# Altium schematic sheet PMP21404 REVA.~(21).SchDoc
size 431 x 279 mm; Date: Not shown in title block; ApprovedBy: Not shown in title block; CheckedBy: Not shown in title block; Author: Not shown in title block; CompanyName: Not shown in title block; Engineer: Not shown in title block; Organization: Not shown in title block; Address1: Not shown in title block; Address2: Not shown in title block; Address3: Not shown in title block; Address4: Not shown in title block; DocumentNumber: 1; Revision: Use project parameter SCH_Rev; SheetNumber: 1; SheetTotal: 1; PageSetup: Record=PageOptions¦CenterHorizontal=True¦CenterVertical=True¦PrintScale=1.00¦XCorrection=1.00¦YCorrection=1.00¦PrintKind=0¦BorderSize=5000000¦LeftOffset=0¦BottomOffset=0¦Orientation=2¦PaperLength=1000¦PaperWidth=1000¦Scale=100¦PaperSource=15¦PrintQuality=600¦MediaType=1¦DitherType=10¦PaperKind=Letter¦PrintScaleMode=1
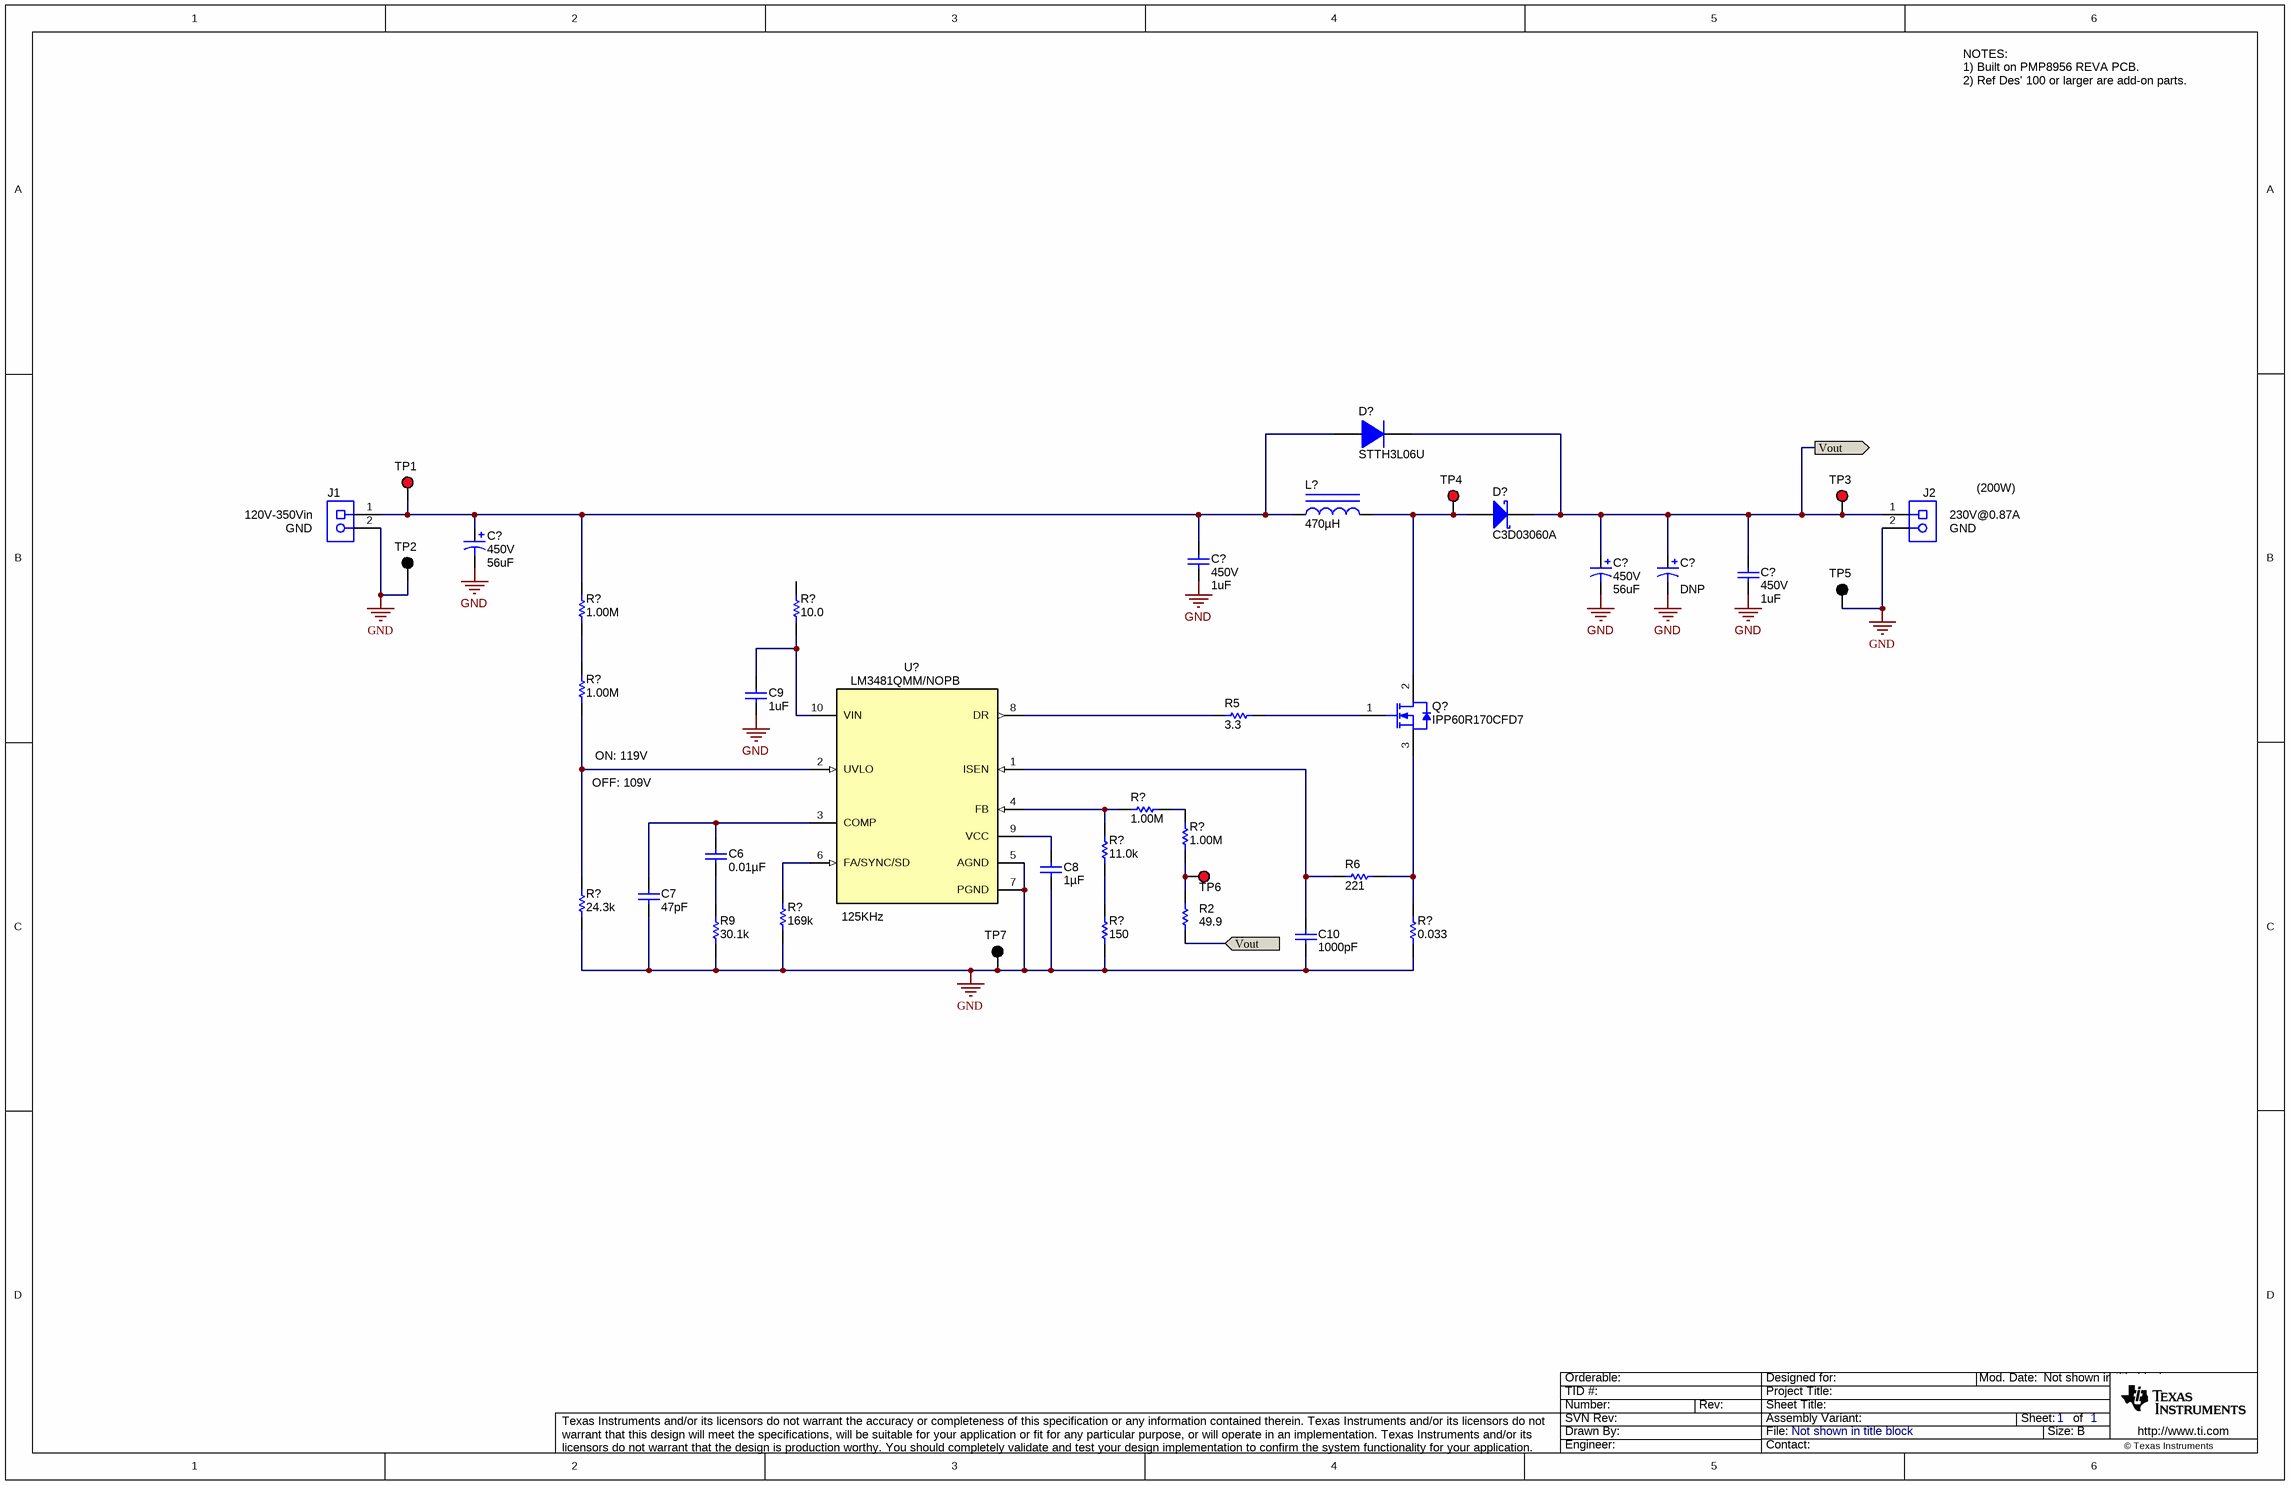
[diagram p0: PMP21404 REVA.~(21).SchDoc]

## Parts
(Parts that share a designator on the sheet are numbered #1, #2 ... from top to bottom, then left to right.)
C6  ValueDisplayed: 0.01µF  [0603]  (hidden comment: C1608X7R1H103K)
C7  ValueDisplayed: 47pF  [0603]  (hidden comment: C1608C0G1H470J)
C8  ValueDisplayed: 1µF  [0603L]  (hidden comment: C1608X7R1C105K)
C9  ValueDisplayed: 1uF  [0805L]  (hidden comment: Capacitor)
C10  ValueDisplayed: 1000pF  [0603L]  (hidden comment: C1608X7R1H102K)
C?#1  VDC_V: 450V  ValueDisplayed: 56uF  [Nichicon_2000x2500_Snap]  (hidden comment: LLS2W560MELY)
C?#2  VDC_V: 450V  ValueDisplayed: 1uF  [MPK_1800x950]  (hidden comment: 450MPK105J)
C?#3  VDC_V: 450V  ValueDisplayed: 56uF  [Nichicon_2000x2500_Snap]  (hidden comment: LLS2W560MELY)
C?#4  ValueDisplayed: DNP  [Nichicon_2000x2500_Snap]
C?#5  VDC_V: 450V  ValueDisplayed: 1uF  [MPK_1800x950]  (hidden comment: 450MPK105J)
D?#1  STTH3L06U  [SMB]
D?#2  C3D03060A  [TO-220-2]
J1  Receptacle_2x1  [TERM_BLK_ED555-2DS]  (value not drawn)
J2  Receptacle_2x1  [TERM_BLK_ED555-2DS]  (value not drawn)
L?  ValueDisplayed: 470µH  [Renco_RL1256-3_Pitch_750]  (hidden comment: RL-1256-3-470)
Q?  IPP60R170CFD7  [TO-220AB]
R2  value 49.9  [0603L]  (hidden comment: Resistor)
R5  ValueDisplayed: 3.3  [0603]  (hidden comment: Resistor)
R6  value 221  [0603L]  (hidden comment: Resistor)
R9  ValueDisplayed: 30.1k  [0603]  (hidden comment: Resistor)
R?#1  ValueDisplayed: 1.00M  [1206]  (hidden comment: CRCW12061M00FKEA)
R?#2  ValueDisplayed: 10.0  [0603]  (hidden comment: CRCW060310R0FKEA)
R?#3  ValueDisplayed: 1.00M  [1206]  (hidden comment: CRCW12061M00FKEA)
R?#4  ValueDisplayed: 1.00M  [1206]  (hidden comment: CRCW12061M00FKEA)
R?#5  ValueDisplayed: 1.00M  [1206]  (hidden comment: CRCW12061M00FKEA)
R?#6  ValueDisplayed: 11.0k  [0603]  (hidden comment: CRCW060311K0FKEA)
R?#7  ValueDisplayed: 24.3k  [0603]  (hidden comment: CRCW060324K3FKEA)
R?#8  ValueDisplayed: 169k  [0603]  (hidden comment: CRCW0603169KFKEA)
R?#9  ValueDisplayed: 150  [0603]  (hidden comment: CRCW0603150RFKEA)
R?#10  ValueDisplayed: 0.033  [1206]  (hidden comment: ERJ-8CWFR033V)
TP1  5000  [Keystone5000]  (value not drawn)
TP2  5001  [Keystone5001]  (value not drawn)
TP3  5000  [Keystone5000]  (value not drawn)
TP4  5000  [Keystone5000]  (value not drawn)
TP5  5001  [Keystone5001]  (value not drawn)
TP6  5000  [Keystone5000]  (value not drawn)
TP7  5001  [Keystone5001]  (value not drawn)
U?  LM3481QMM/NOPB  [DGS0010A_N]

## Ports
Vout

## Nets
GND: C7.2 C8.2 C9.2 C10.2 C?#1.2(-) C?#2.2 C?#3.2(-) C?#4.2(-) C?#5.2 J1.2 J2.2 R9.1 R?#7.1 R?#8.1 R?#9.1 R?#10.1 TP2.1 TP5.1 TP7.1 U?.5(AGND) U?.7(PGND)
Vout: C?#3.1(+) C?#4.1(+) C?#5.1 D?#1.1(K) D?#2.1(K) J2.1 R2.1 TP3.1 ; port Vout
NetC6_1: C6.1 C7.1 U?.3(COMP)
NetC6_2: C6.2 R9.2
NetC8_1: C8.1 U?.9(VCC)
NetC9_1: C9.1 R?#2.1 U?.10(VIN)
NetC10_1: C10.1 R6.2 U?.1(ISEN)
NetC?#1_1: C?#1.1(+) C?#2.1 D?#1.2(A) J1.1 L?.1 R?#1.2 TP1.1
NetD?#2_2: D?#2.2(A) L?.2 Q?.2(D) TP4.1
NetQ?_1: Q?.1(G) R5.2
NetQ?_3: Q?.3(S) R6.1 R?#10.2
NetR2_2: R2.2 R?#5.1 TP6.1
NetR5_1: R5.1 U?.8(DR)
NetR?#1_1: R?#1.1 R?#3.2
NetR?#3_1: R?#3.1 R?#7.2 U?.2(UVLO)
NetR?#4_1: R?#4.1 R?#6.2 U?.4(FB)
NetR?#4_2: R?#4.2 R?#5.2
NetR?#6_1: R?#6.1 R?#9.2
NetR?#8_2: R?#8.2 U?.6(FA/SYNC/SD)

Not connected (* = marked no-connect by the designer): R?#2 2

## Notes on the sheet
- NOTES:
  1) Built on PMP8956 REVA PCB.
  2) Ref Des' 100 or larger are add-on parts.
- (200W)
- (near J1) 120V-350Vin
- (near J1) GND
- (near J2) 230V@0.87A
- (near J2) GND
- (near R?#3) ON: 119V
- OFF: 109V
- (near U?) 125KHz

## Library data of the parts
C6 = C1608X7R1H103K: CAP, CERM, 0.01uF, 50V, +/-10%, X7R, 0603; Manufacturer: TDK; Polarized: N; CompType: Capacitor; U/M: EA; Cap_F: 0.00000001; Tolerance_%: 10; ESR_Ohm: 0.0539; Value1: 0.0539 ohm; VDC_V: 50; TaMin_C: -55; TaMax_C: 125
C7 = C1608C0G1H470J: CAP, CERM, 47pF, 50V, +/-5%, C0G/NP0, 0603; Manufacturer: TDK; Polarized: N; CompType: Capacitor; U/M: EA; Cap_F: 0.000000000047; Tolerance_%: 5; ESR_Ohm: 0.22; Value1: 0.22 ohm; VDC_V: 50; TaMin_C: -55; TaMax_C: 125
C8 = C1608X7R1C105K: CAP, CERM, 1uF, 16V, +/-10%, X7R, 0603; Manufacturer: TDK; Polarized: N; CompType: Capacitor; U/M: EA; Cap_F: 0.000001; Tolerance_%: 10; ESR_Ohm: 0.0057; Value1: 0.0057 ohm; VDC_V: 16; TaMin_C: -55; TaMax_C: 125; Cap_Case: 0603
C9 = CMP-0008350-2: CAP, CERM, 1 uF, 50 V, +/- 10%, X7R, 0805; PartNumber: GRM21BR71H105KA12L; Manufacturer: MuRata; Polarized: N; Value: 1uF; U/M: EA; Cap_F: 1µF; Value1: Unknown; VDC_V: 50V; TaMin_C: -55°C; TaMax_C: 125°C; Cap_Case: 0805; AEC Category: Q200; SizeArea_mm2: 2.5; SizeAreaWB_mm2: 6.75; SizeX_mm: 2; SizeY_mm: 1.25; SizeZ_mm: 1.45
C10 = C1608X7R1H102K: CAP, CERM, 1000pF, 50V, +/-10%, X7R, 0603; Manufacturer: TDK; Polarized: N; CompType: Capacitor; U/M: EA; Cap_F: 0.000000001; Tolerance_%: 10; ESR_Ohm: 0.24; Value1: 0.24 ohm; VDC_V: 50; TaMin_C: -55; TaMax_C: 125; Cap_Case: 0603
C?#1 C?#3 = CMP-0010119-2: CAP, AL, 56 uF, 450 V, +/- 20%, TH; Manufacturer: Nichicon; TaMin_C: -25°C; Polarized: Y; SizeAreaWB_mm2: 484; Value1: Unknown; U/M: EA; Value: 56uF; TaMax_C: 85°C; SizeZ_mm: 27; SizeX_mm: 20; Cap_Case: 20x25mm; SizeArea_mm2: 400; CompType: Capacitor; AEC Qualified: N; Cap_F: 56µF; IRMS_A: 6.1dA; AEC Category: Q200
C?#2 C?#5 = CMP-0012307-3: CAP, Film, 1 uF, 450 V, +/- 5%, TH; Manufacturer: Rubycon; TaMin_C: -40°C; Polarized: N; Value1: Unknown; Value: 1uF; TaMax_C: 105°C; Cap_Case: 18x9.5mm; Cap_F: 1µF; AEC Category: Q200
C?#4 = CMP-0010119-2: CAP, AL, DNP; TaMin_C: -25°C; Polarized: Y; SizeAreaWB_mm2: 484; Value1: Unknown; U/M: EA; TaMax_C: 85°C; Tolerance_%: 20%; SizeZ_mm: 27; SizeX_mm: 20; Cap_Case: 20x25mm; SizeArea_mm2: 400; CompType: Capacitor; AEC Qualified: N; AEC Category: Q200
D?#1 = CMP-0077014-1: Diode, Ultrafast, 600 V, 3 A, SMB; Manufacturer: STMicroelectronics; SizeAreaWB_mm2: 44.156; Vr_V: 600V; SizeArea_mm2: 21.336; TJmax_C: 175°C; AEC Category: Q101; Value: 600V; SizeZ_mm: 2.6; Green_REACh: Incomplete; Io_A: 3A; Vf_V: 1.3V; SizeY_mm: 3.81; Green_Lifecycle: Not Set; U/M: EA; SizeX_mm: 5.6
D?#2 = CMP-0079543-1: Diode, Schottky, 600 V, 11 A, AEC-Q101, TH; Manufacturer: Cree; SizeAreaWB_mm2: 77.630025; Vr_V: 600V; SizeArea_mm2: 44.650025; AEC Qualified: Y; TJmax_C: 175°C; AEC Category: Q101; Value: 600V; SizeZ_mm: 20; Green_REACh: Incomplete; Io_A: 11A; SizeY_mm: 4.445; Green_Lifecycle: Active; SizeX_mm: 10.045; RJC_CperW: 3.2
J1 J2 = CMP-0074913-1: Terminal Block, 3.5mm Pitch, 2x1, TH; PartNumber: ED555/2DS; Manufacturer: On-Shore Technology; Cert_CULUS: Y; CNHeader: False; ContactFinish: Brass; CT: True; Current_A: 6A; Gender: Female; Green_Lifecycle: Active; Green_REACh: Passed; Pitch_mm: 3.5; Row_Count: 1; Shrouded: N; Voltage_V: 150V
L? = CMP-0077831-1: Inductor, 470 µH, 4 A, 0.187 ohm, TH; Manufacturer: Renco Electronics; SizeAreaWB_mm2: 896.4036; Irms: 4A @ 40C rise; SizeArea_mm2: 780.6436; AEC Qualified: N; AEC Category: Q200; Value: 470uH; SizeZ_mm: 21.59; Imax_A: 4A; SizeY_mm: 27.94; Isat: 6A @ 5% inductance drop; DCR_ohm: 1.87d
Q? = CMP-0001174-3: MOSFET, N-CH, 600 V, 51 A, TO-220AB; Alternate Manufacturer: None; Manufacturer: Infineon Technologies; SizeZ_mm: 19.4; ChType: N; Value2: 28 nC; VdsMax_V: 600V; SizeX_mm: 10.2; SizeY_mm: 4.5; Vgs_V: 20V; Value: 600V; SizeArea_mm2: 45.9; AEC Category: Q101; IdsMax_A: 51A; SizeAreaWB_mm2: 79.3; U/M: EA; QgTyp_nC: 28
R2 = CMP-0022448-4: RES, 49.9, 1%, 0.1 W, AEC-Q200 Grade 0, 0603; PartNumber: CRCW060349R9FKEA; Manufacturer: Vishay-Dale; Value_Code: 49R9; Power_W: 100mW; Value2: 0.1W; VDC_V: 75V; TempCo: 100 ppm/C; EIA_Code: E96; AEC Category: Q200; AEC Grade: 0; AEC Qualified: Y; SizeArea_mm2: 1.28; SizeX_mm: 1.6; SizeY_mm: 0.8; SizeZ_mm: 1
R5 = CMP-0025805-4: RES, 3.3, 5%, 0.1 W, AEC-Q200 Grade 0, 0603; PartNumber: CRCW06033R30JNEA; Manufacturer: Vishay-Dale; Value: 3.3; Value_Code: 3R30; Power_W: 100mW; Value2: 0.1W; VDC_V: 75V; TempCo: 200 ppm/C; EIA_Code: E24; AEC Category: Q200; AEC Qualified: Y; AEC Grade: 0; SizeArea_mm2: 1.28; SizeX_mm: 1.6; SizeY_mm: 0.8; SizeZ_mm: 1
R6 = CMP-0022217-5: RES, 221, 1%, 0.1 W, AEC-Q200 Grade 0, 0603; PartNumber: CRCW0603221RFKEA; Manufacturer: Vishay-Dale; Value_Code: 221R; Power_W: 100mW; Value2: 0.1W; VDC_V: 75V; TempCo: 100 ppm/C; EIA_Code: E96; AEC Category: Q200; AEC Grade: 0; AEC Qualified: Y; SizeArea_mm2: 1.28; SizeX_mm: 1.6; SizeY_mm: 0.8; SizeZ_mm: 1
R9 = CMP-0022324-4: RES, 30.1 k, 1%, 0.1 W, AEC-Q200 Grade 0, 0603; PartNumber: CRCW060330K1FKEA; Manufacturer: Vishay-Dale; Value: 30.1k; Value_Code: 30k1; Power_W: 100mW; Value2: 0.1W; VDC_V: 75V; TempCo: 100 ppm/C; EIA_Code: E96; AEC Category: Q200; AEC Qualified: Y; AEC Grade: 0; SizeArea_mm2: 1.28; SizeX_mm: 1.6; SizeY_mm: 0.8; SizeZ_mm: 1
R?#1 R?#3-R?#5 = CMP-0016716-3: RES, 1.00 M, 1%, 0.25 W, AEC-Q200 Grade 0, 1206; Manufacturer: Vishay-Dale; Power_W: 250mW; TempCo: 100 ppm/C; Value_Code: 1M00; Value: 1.00Meg; EIA_Code: E96; Res_ohm: 1M; SizeX_mm: 3.2; SizeY_mm: 1.6; SizeZ_mm: 1.35; Value2: 0.25W; SizeArea_mm2: 5.12; AEC Qualified: Y; VDC_V: 200V; AEC Category: Q200; AEC Grade: 0
R?#2 = CMP-0022003-4: RES, 10.0, 1%, 0.1 W, AEC-Q200 Grade 0, 0603; Manufacturer: Vishay-Dale; Power_W: 100mW; TempCo: 100 ppm/C; Value_Code: 10R0; Value: 10.0; EIA_Code: E96; Res_ohm: 10; SizeX_mm: 1.6; SizeY_mm: 0.8; SizeZ_mm: 1; Value2: 0.1W; SizeArea_mm2: 1.28; AEC Qualified: Y; VDC_V: 75V; AEC Category: Q200; AEC Grade: 0
R?#6 = CMP-0022016-4: RES, 11.0 k, 1%, 0.1 W, AEC-Q200 Grade 0, 0603; Manufacturer: Vishay-Dale; Power_W: 100mW; TempCo: 100 ppm/C; Value_Code: 11k0; Value: 11.0k; EIA_Code: E96; Res_ohm: 11k; SizeX_mm: 1.6; SizeY_mm: 0.8; SizeZ_mm: 1; Value2: 0.1W; SizeArea_mm2: 1.28; AEC Qualified: Y; VDC_V: 75V; AEC Category: Q200; AEC Grade: 0
R?#7 = CMP-0022236-4: RES, 24.3 k, 1%, 0.1 W, AEC-Q200 Grade 0, 0603; Manufacturer: Vishay-Dale; Power_W: 100mW; TempCo: 100 ppm/C; Value_Code: 24k3; Value: 24.3k; EIA_Code: E96; SizeX_mm: 1.6; SizeY_mm: 0.8; SizeZ_mm: 1; Value2: 0.1W; SizeArea_mm2: 1.28; AEC Qualified: Y; VDC_V: 75V; AEC Category: Q200; AEC Grade: 0
R?#8 = CMP-0022077-4: RES, 169 k, 1%, 0.1 W, AEC-Q200 Grade 0, 0603; Manufacturer: Vishay-Dale; Power_W: 100mW; TempCo: 100 ppm/C; Value: 169k; EIA_Code: E96; SizeX_mm: 1.6; SizeY_mm: 0.8; SizeZ_mm: 1; Value2: 0.1W; SizeArea_mm2: 1.28; AEC Qualified: Y; VDC_V: 75V; AEC Category: Q200; AEC Grade: 0
R?#9 = CMP-0022061-5: RES, 150, 1%, 0.1 W, AEC-Q200 Grade 0, 0603; Manufacturer: Vishay-Dale; Power_W: 100mW; TempCo: 100 ppm/C; Value_Code: 150R; Value: 150; EIA_Code: E96; SizeX_mm: 1.6; SizeY_mm: 0.8; SizeZ_mm: 1; Value2: 0.1W; SizeArea_mm2: 1.28; AEC Qualified: Y; VDC_V: 75V; AEC Category: Q200; AEC Grade: 0
R?#10 = CMP-0017280-2: RES, 0.033, 1%, 1 W, AEC-Q200 Grade 0, 1206; Manufacturer: Panasonic; Power_W: 1W; TempCo: 50 ppm/C; Value_Code: R033; U/M: EA; Value: 0.033; EIA_Code: E96; SizeX_mm: 3.2; SizeY_mm: 1.6; SizeZ_mm: 1.35; SizeArea_mm2: 5.12; AEC Qualified: Y; AEC Grade: 0; AEC Category: Q200
TP1 TP3 TP4 TP6 = CMP-0055137-1: Test Point, Miniature, Red, TH; Manufacturer: Keystone; CNHeader: FALSE; ContactFinish: Silver; CT: TRUE; Green_Lifecycle: Active; Green_REACh: Passed
TP2 TP5 TP7 = CMP-0055138-1: Test Point, Miniature, Black, TH; Manufacturer: Keystone; CNHeader: FALSE; ContactFinish: Silver; CT: TRUE; Green_Lifecycle: Active; Green_REACh: Passed
U? = CMP-0071928-2: High Efficiency Low-Side N-Channel Controller for Switching Regulators, AEC-Q100 Grade 1, 10-pin Mini SOIC, 1000 Reel; Manufacturer: Texas Instruments; Alternate PartNumber: LM3481QMMX/NOPB; CompType: IC; AEC Category: Q200; AEC Qualified: Y; SizeAreaWB_mm2: 23.6; SizeArea_mm2: 14.7; SizeX_mm: 4.9; SizeY_mm: 3; SizeZ_mm: 1.1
